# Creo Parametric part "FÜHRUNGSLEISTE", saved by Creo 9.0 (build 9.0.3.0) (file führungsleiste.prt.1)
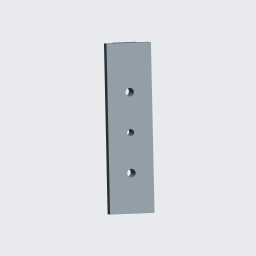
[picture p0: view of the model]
Units: millimeter Kilogram Sec (mmKs); MM, KILOGRAM, SECS
Materials in the file: STAHL

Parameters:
  WERKSTOFF = "Stahl"
  ERSTELLER = "ARINDA"
  BENENNUNG = "XXX"
  TEILETYP = "K"
  PTC_MASTER_MATERIAL = "STAHL"
  SCHRAUBEN_GROESSE = "M3x.5"
  METRISCH = "JA"

Other parameters: MASSE, STEIGUNG, BOHR_DURCHM, GEWINDEDURCHMESSER, GEWINDEGÄNGE_PRO_INCH

Created from: ARINDA_STARTTEIL.PRT

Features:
  1. coordinate system
  2. datum plane "RECHTS_Y-Z"
  3. datum plane "OBEN_X-Z"
  4. datum plane "VORNE_X-Y"
  5. datum axis
  6. datum axis
  7. datum axis
  8. datum point "PNT0"
  9. extrusion "Profil 1"
  10. hole "Bohrung 1"
  11. sketch "Skizze 1"
  12. pattern "Muster 1"
  13. hole "Bohrung 2"
  14. hole "Bohrung 2 [9]"

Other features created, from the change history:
  coordinate system "CS1"

Other named items: A_X, A_Y, A_Z, CS0

Layers: 01_ACHSEN, 01_ACHSEN_STD, 01_EBENEN_STD, 01_KOORDSYS_STD, 01_KURVEN, 01_PUNKTE_STD, GEWINDE, SAMMELFLÄCHEN, VOLUMENGEOMETRIE

Notes: M3x.5 | GEWINDEBOHREN | DURCH |  BOHREN (  | 2.500 | DURCH |   -(  |  ) BOHRUNG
